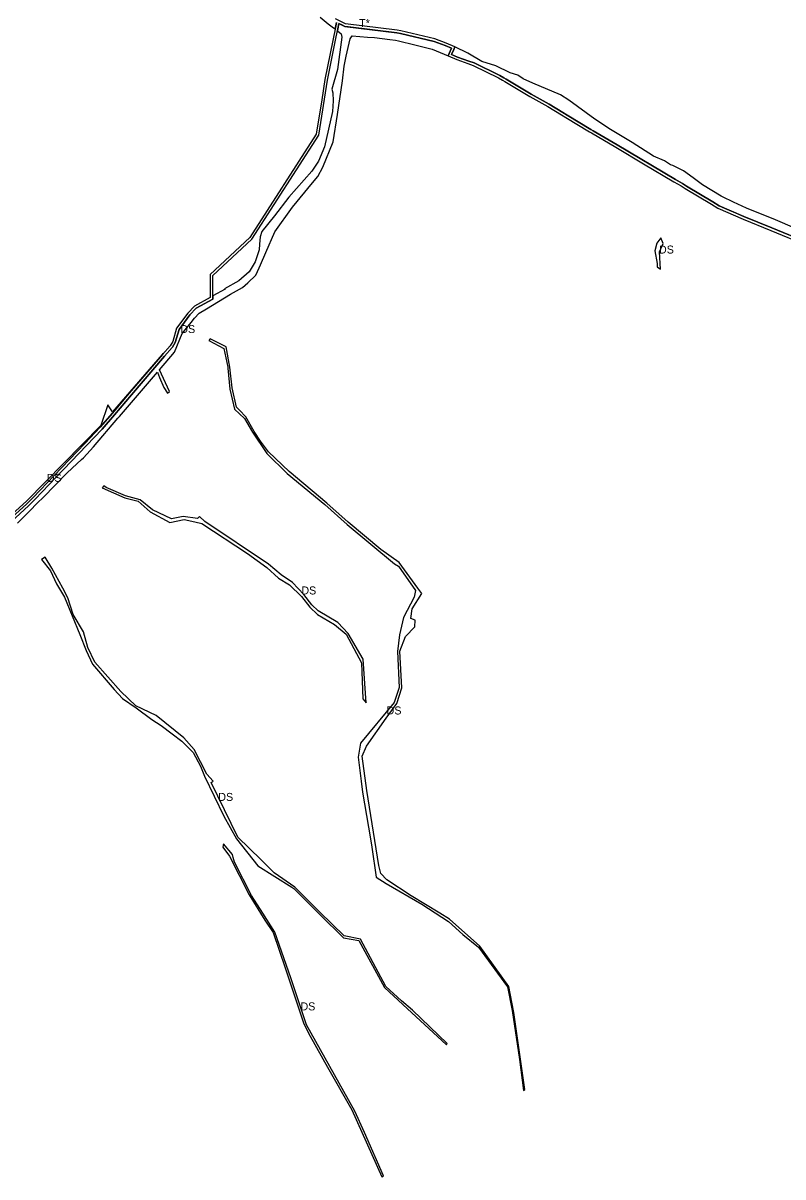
# Model space of a CAD drawing. Extents: x -477304 to -465641, y -1159113 to -1149285.
# Drawn here: x -471518 to -470664, y -1155901 to -1154603 of the extents above; entities that cross this region are included whole.
import ezdxf

# ---------------------------------------------------------------- set-up
doc = ezdxf.new("R2010")
doc.units = 0
doc.layers.add('35', color=7, linetype='Continuous')
doc.layers.add('4', color=7, linetype='Continuous')

msp = doc.modelspace()

# ---------------------------------------------------------------- linework, layer by layer
at = {"layer": '35'}
for p, q in [((-471184.5, -1154596.4), (-471175.4, -1154604.1)), ((-471175.4, -1154604.1), (-471169.4, -1154608.4)), ((-471169.4, -1154608.4), (-471167.6, -1154609.6)), ((-471167.6, -1154609.6), (-471167.3, -1154608.1)), ((-471167.3, -1154608.1), (-471166.1, -1154602.3)), ((-471165, -1154611.8), (-471160.9, -1154615.2)), ((-471159.4, -1154605.6), (-471163.4, -1154603.7)), ((-471155.1, -1154640.2), (-471150.8, -1154620.7)), ((-471150.8, -1154620.7), (-471148.5, -1154617.6)), ((-471148.5, -1154617.6), (-471131.1, -1154619.1)), ((-471131.1, -1154619.1), (-471123.4, -1154619.4)), ((-471123.4, -1154619.4), (-471106.3, -1154621.6)), ((-471106.3, -1154621.6), (-471099.9, -1154622.4)), ((-471099.9, -1154622.4), (-471096.4, -1154622.9)), ((-471096.4, -1154622.9), (-471078, -1154627.5)), ((-471078, -1154627.5), (-471058.5, -1154632.5)), ((-471058.5, -1154632.5), (-471040.6, -1154640.1)), ((-471040.6, -1154640.1), (-471039.4, -1154637.3)), ((-471039.4, -1154637.3), (-471037, -1154631.5)), ((-471034.3, -1154632.8), (-471036.7, -1154638.5)), ((-471036.7, -1154638.5), (-471029.9, -1154641.3)), ((-471033.1, -1154630), (-471034.3, -1154632.8)), ((-471159.4, -1154668.1), (-471157.6, -1154651.6)), ((-471157.6, -1154651.6), (-471155.1, -1154640.2)), ((-471029.9, -1154641.3), (-471017.3, -1154645.8)), ((-470956.4, -1154665.7), (-470962.3, -1154661.8)), ((-471171.4, -1154677.6), (-471170.4, -1154681.6)), ((-471164.8, -1154706.1), (-471159.4, -1154668.1)), ((-470945.2, -1154670.5), (-470956.4, -1154665.7)), ((-471169.9, -1154690.4), (-471170.7, -1154702.4)), ((-471170.4, -1154681.6), (-471169.9, -1154690.4)), ((-471170.7, -1154702.4), (-471179.7, -1154742.1)), ((-470906.8, -1154706.6), (-470880.1, -1154722.7)), ((-470880.1, -1154722.7), (-470877.7, -1154724.1)), ((-470877.7, -1154724.1), (-470850.7, -1154740.1)), ((-470833.8, -1154737.3), (-470857.9, -1154722.9)), ((-470809.7, -1154752.9), (-470833.8, -1154737.3)), ((-470797.3, -1154757.9), (-470809.7, -1154752.9)), ((-471187.1, -1154775.6), (-471181.3, -1154765.1)), ((-471193.9, -1154769.5), (-471219.7, -1154798.8)), ((-471193.1, -1154782.8), (-471187.1, -1154775.6)), ((-470765.3, -1154777.3), (-470776.1, -1154769.4)), ((-470754.5, -1154784.9), (-470765.3, -1154777.3)), ((-471215.7, -1154810.1), (-471193.1, -1154782.8)), ((-471219.7, -1154798.8), (-471235.8, -1154820)), ((-470719.7, -1154804.5), (-470732.2, -1154798.6)), ((-470705.2, -1154811.3), (-470719.7, -1154804.5)), ((-471235.8, -1154820), (-471250, -1154837.5)), ((-471235.4, -1154838), (-471215.7, -1154810.1)), ((-470736, -1154808.6), (-470730, -1154811.3)), ((-470730, -1154811.3), (-470727.3, -1154812.5)), ((-470727.3, -1154812.5), (-470717.7, -1154816.6)), ((-470717.7, -1154816.6), (-470708, -1154820.8)), ((-471252.1, -1154843.4), (-471252.8, -1154851.7)), ((-471250, -1154837.5), (-471252.1, -1154843.4)), ((-471245.7, -1154861.3), (-471235.4, -1154838)), ((-470801.6, -1154844.8), (-470806, -1154850.6)), ((-471253.1, -1154858.2), (-471257.6, -1154871.7)), ((-471252.8, -1154851.7), (-471253.1, -1154858.2)), ((-471257.6, -1154871.7), (-471264.2, -1154882.9)), ((-471251.7, -1154875.1), (-471245.7, -1154861.3)), ((-471264.2, -1154882.9), (-471276, -1154893)), ((-471256.8, -1154886.5), (-471253.2, -1154878.5)), ((-471253.2, -1154878.5), (-471251.7, -1154875.1)), ((-470805.5, -1154873.5), (-470805.7, -1154877.3)), ((-471276, -1154893), (-471291.9, -1154901.8)), ((-471271.8, -1154900.4), (-471265.8, -1154895.2)), ((-471265.8, -1154895.2), (-471256.8, -1154886.5)), ((-471312.1, -1154924.3), (-471285.1, -1154908.1)), ((-471291.4, -1154902.4), (-471305.3, -1154910)), ((-471305.3, -1154910), (-471305.3, -1154913.5)), ((-471291.9, -1154901.8), (-471291.4, -1154902.4)), ((-471285.1, -1154908.1), (-471271.8, -1154900.4)), ((-471320.5, -1154929.3), (-471312.1, -1154924.3)), ((-471329.3, -1154939.7), (-471325.6, -1154935)), ((-471325.6, -1154935), (-471320.5, -1154929.3)), ((-471308, -1154958.1), (-471309.6, -1154960.2)), ((-471290.2, -1154967.1), (-471308, -1154958.1)), ((-471362.2, -1154975.7), (-471417.9, -1155040.4)), ((-471399, -1155019.2), (-471361.7, -1154975.7)), ((-471360.8, -1154974.8), (-471362.2, -1154975.7)), ((-471361.7, -1154975.7), (-471360.8, -1154974.8)), ((-471285.9, -1154990.2), (-471290.2, -1154967.1)), ((-471410, -1155045.4), (-471367.4, -1154995.7)), ((-471367.4, -1154995.7), (-471365, -1155001.6)), ((-471353.9, -1155017.3), (-471365.1, -1154993)), ((-471365, -1155001.6), (-471360.2, -1155013.1)), ((-471283.4, -1155013.3), (-471285.9, -1154990.2)), ((-471360.2, -1155013.1), (-471356.2, -1155019.4)), ((-471285.9, -1155014.7), (-471280.6, -1155037.4)), ((-471278.6, -1155035.1), (-471283.4, -1155013.3)), ((-471356.2, -1155019.4), (-471353.9, -1155017.3)), ((-471423.2, -1155032.4), (-471431, -1155055.7)), ((-471417.9, -1155040.4), (-471423.2, -1155032.4)), ((-471275.3, -1155038.5), (-471278.6, -1155035.1)), ((-471415.8, -1155043.7), (-471429.4, -1155059.7)), ((-471411.8, -1155047.5), (-471410, -1155045.4)), ((-471431, -1155055.7), (-471514.7, -1155140.7)), ((-471449.2, -1155076.1), (-471431.6, -1155057.7)), ((-471251.7, -1155073.4), (-471258.5, -1155062.6)), ((-471242.6, -1155085.4), (-471251.7, -1155073.4)), ((-471452.7, -1155093.8), (-471450.6, -1155091.9)), ((-471496, -1155136.6), (-471468.8, -1155108.8)), ((-471427.5, -1155123.7), (-471429.7, -1155125.8)), ((-471429.7, -1155125.8), (-471404.1, -1155136.9)), ((-471514.7, -1155140.7), (-471548.2, -1155171.2)), ((-471502.1, -1155142.8), (-471496, -1155136.6)), ((-471404.1, -1155136.9), (-471389, -1155140.9)), ((-471389, -1155140.9), (-471375.4, -1155152.8)), ((-471152.9, -1155164.4), (-471176.9, -1155143.1)), ((-471524.9, -1155165.7), (-471513.5, -1155154.3)), ((-471375.4, -1155152.8), (-471353.4, -1155164.7)), ((-471320, -1155157.9), (-471322.2, -1155160.4)), ((-471314.1, -1155163.6), (-471320, -1155157.9)), ((-471353.4, -1155164.7), (-471337.2, -1155161.5)), ((-471317.5, -1155165.8), (-471266.3, -1155199.7)), ((-471116.1, -1155195.1), (-471152.9, -1155164.4)), ((-471493.6, -1155203.7), (-471497.9, -1155206.5)), ((-471497.9, -1155206.5), (-471487.6, -1155219.2)), ((-471486, -1155216.3), (-471493.6, -1155203.7)), ((-471473.8, -1155238.6), (-471486, -1155216.3)), ((-471231.3, -1155227.4), (-471218.8, -1155234.7)), ((-471215.5, -1155232.3), (-471228.3, -1155223.7)), ((-471218.8, -1155234.7), (-471205.6, -1155248.1)), ((-471468, -1155249.4), (-471473.8, -1155238.6)), ((-471471.7, -1155248.7), (-471454.6, -1155290.8)), ((-471205.6, -1155248.1), (-471196.1, -1155259.9)), ((-471077.2, -1155241.2), (-471078.9, -1155248.6)), ((-471164.6, -1155277.2), (-471186.8, -1155264.2)), ((-471077.7, -1155274.8), (-471082.4, -1155272.8)), ((-471445.7, -1155305.2), (-471450.5, -1155287.9)), ((-471153, -1155289.5), (-471164.6, -1155277.2)), ((-471097.7, -1155309.9), (-471095.7, -1155350.5)), ((-471098.3, -1155368.5), (-471092.8, -1155350.8)), ((-471110.1, -1155385), (-471098.3, -1155368.5)), ((-471373.7, -1155386.2), (-471363.2, -1155393)), ((-471132.5, -1155416.4), (-471110.1, -1155385)), ((-471363.2, -1155393), (-471350.8, -1155402.4)), ((-471139.2, -1155412.9), (-471141.6, -1155428.6)), ((-471327.4, -1155423.3), (-471319.1, -1155439)), ((-471319.1, -1155439), (-471314.5, -1155450.1)), ((-471314.5, -1155450.1), (-471292.8, -1155495.1)), ((-471118.6, -1155550.5), (-471132.1, -1155466.1)), ((-471292.8, -1155495.1), (-471278.5, -1155520.7)), ((-471278.5, -1155520.7), (-471254.4, -1155550.8)), ((-471128, -1155520.7), (-471126.5, -1155529.8)), ((-471293.2, -1155526.1), (-471293.9, -1155529.9)), ((-471293.9, -1155529.9), (-471286.3, -1155540)), ((-471283.2, -1155538.3), (-471293.2, -1155526.1)), ((-471286.3, -1155540), (-471264.4, -1155583.7)), ((-471282.3, -1155541.4), (-471283.2, -1155538.3)), ((-471254.4, -1155550.8), (-471216.4, -1155574.8)), ((-471116.3, -1155559.4), (-471118.6, -1155550.5)), ((-471109.6, -1155566.7), (-471116.3, -1155559.4)), ((-471082.1, -1155584.5), (-471109.6, -1155566.7)), ((-471264.4, -1155583.7), (-471246.7, -1155612.1)), ((-471249.1, -1155604.3), (-471261.8, -1155584.4)), ((-471216.4, -1155574.8), (-471214, -1155576.3)), ((-471184.9, -1155603), (-471213.1, -1155574.9)), ((-471050, -1155604.1), (-471082.1, -1155584.5)), ((-470972.3, -1155686.5), (-471005, -1155641.4)), ((-471223.8, -1155665.6), (-471203, -1155728.5)), ((-470973.8, -1155687), (-470968.6, -1155713.7)), ((-470968.6, -1155713.7), (-470960.5, -1155768.8)), ((-471203, -1155728.5), (-471195.6, -1155742.6)), ((-471195.6, -1155742.6), (-471176.1, -1155777.5)), ((-471042.6, -1155752.2), (-471041.7, -1155750.9)), ((-471176.1, -1155777.5), (-471148.9, -1155825.5)), ((-471145.6, -1155827), (-471152.7, -1155814.2)), ((-471134.8, -1155850.8), (-471145.6, -1155827)), ((-471113.2, -1155899.5), (-471134.8, -1155850.8))]:
    msp.add_line(p, q, dxfattribs=at)
for points in [[(-471163.4, -1154603.7), (-471164.5, -1154609.6), (-471165, -1154611.8)], [(-471152.9, -1154607.4), (-471156.6, -1154607), (-471159.4, -1154605.6)], [(-471037, -1154631.5), (-471043.9, -1154628.4), (-471056.3, -1154623.7), (-471094.3, -1154614.7), (-471098.2, -1154614.2), (-471152.9, -1154607.4)], [(-471160.9, -1154615.2), (-471160.2, -1154618.9), (-471164.9, -1154655.3), (-471171.4, -1154677.6)], [(-470962.3, -1154661.8), (-470971, -1154659.1), (-470987, -1154651.2), (-471002.6, -1154646.2), (-471018.3, -1154636.8), (-471033.1, -1154630)], [(-471017.3, -1154645.8), (-471011.4, -1154647.9), (-470982.3, -1154662.1)], [(-470982.3, -1154662.1), (-470977.8, -1154664.8), (-470975.2, -1154666.2), (-470947.4, -1154682.9)], [(-470905, -1154689.8), (-470914.2, -1154683.9), (-470945.2, -1154670.5)], [(-470947.4, -1154682.9), (-470927.1, -1154694.4), (-470911.6, -1154703.7), (-470906.8, -1154706.6)], [(-470857.9, -1154722.9), (-470875.8, -1154711.3), (-470905, -1154689.8)], [(-471181.3, -1154765.1), (-471169.7, -1154736.7), (-471164.8, -1154706.1)], [(-471179.7, -1154742.1), (-471186.5, -1154758.4), (-471193.9, -1154769.5)], [(-470850.7, -1154740.1), (-470785.1, -1154779), (-470777.2, -1154783.7), (-470772.7, -1154786.4)], [(-470776.1, -1154769.4), (-470788, -1154763.1), (-470790.8, -1154762.6), (-470797.3, -1154757.9)], [(-470772.7, -1154786.4), (-470743.2, -1154804.3), (-470736, -1154808.6)], [(-470732.2, -1154798.6), (-470733.6, -1154797.9), (-470754.5, -1154784.9)], [(-470708, -1154820.8), (-470676.7, -1154833.4), (-470636.5, -1154849.9), (-470632.8, -1154851.4)], [(-470650.7, -1154833.6), (-470672.6, -1154824.2), (-470705.2, -1154811.3)], [(-470805.7, -1154877.3), (-470801.8, -1154879.9), (-470803, -1154860.3), (-470798.9, -1154851.1), (-470801.6, -1154844.8)], [(-470806, -1154850.6), (-470808.2, -1154859.2), (-470805.5, -1154873.5)], [(-471305.3, -1154913.5), (-471323.8, -1154923.7), (-471331, -1154931.1)], [(-471331, -1154931.1), (-471343.1, -1154947.7), (-471347.5, -1154962.5), (-471350.6, -1154967.6), (-471350.7, -1154967.9)], [(-471365.1, -1154993), (-471348.2, -1154973.2), (-471339.6, -1154952.2), (-471329.3, -1154939.7)], [(-471309.6, -1154960.2), (-471292.8, -1154968.9), (-471288.3, -1154990.2)], [(-471350.7, -1154967.9), (-471359.4, -1154977.7), (-471396.7, -1155021.2), (-471415.8, -1155043.7)], [(-471288.3, -1154990.2), (-471288.2, -1154991.1), (-471285.9, -1155014.7)], [(-471431.6, -1155057.7), (-471418.1, -1155041.8), (-471399, -1155019.2)], [(-471280.6, -1155037.4), (-471269.5, -1155047.8), (-471260.7, -1155063.3), (-471244.3, -1155087.2), (-471221.6, -1155109.8), (-471179.1, -1155144.4), (-471154.1, -1155167.1), (-471100.8, -1155211.1), (-471096.4, -1155214), (-471077.2, -1155241.2)], [(-471258.5, -1155062.6), (-471268, -1155045.9), (-471275.3, -1155038.5)], [(-471450.6, -1155091.9), (-471439.3, -1155079.6), (-471411.8, -1155047.5)], [(-471429.4, -1155059.7), (-471447.1, -1155078.2), (-471481.2, -1155113.9), (-471504.9, -1155138.7)], [(-471507, -1155136.6), (-471483.4, -1155111.8), (-471449.2, -1155076.1)], [(-471176.9, -1155143.1), (-471219.4, -1155107.5), (-471242.6, -1155085.4)], [(-471468.8, -1155108.8), (-471458, -1155098.8), (-471452.7, -1155093.8)], [(-471386.8, -1155139.2), (-471403.3, -1155134.6), (-471425.2, -1155125.3), (-471427.5, -1155123.7)], [(-471597.2, -1155216), (-471589.1, -1155208.2), (-471582.5, -1155201.6), (-471548, -1155174.3), (-471514.2, -1155143.7), (-471507, -1155136.6)], [(-471504.9, -1155138.7), (-471512.2, -1155145.9), (-471546.1, -1155176.6), (-471580.5, -1155203.9), (-471587, -1155210.4)], [(-471513.5, -1155154.3), (-471511.3, -1155152.1), (-471502.1, -1155142.8)], [(-471351.5, -1155160.7), (-471373, -1155150.6), (-471386.8, -1155139.2)], [(-471322.2, -1155160.4), (-471338.6, -1155158), (-471351.5, -1155160.7)], [(-471337.2, -1155161.5), (-471325.3, -1155164.1), (-471317.5, -1155165.8)], [(-471228.3, -1155223.7), (-471242.6, -1155211.8), (-471314.1, -1155163.6)], [(-471074.5, -1155238.5), (-471095.6, -1155209.9), (-471116.1, -1155195.1)], [(-471266.3, -1155199.7), (-471244.4, -1155215.2), (-471231.3, -1155227.4)], [(-471487.6, -1155219.2), (-471480.8, -1155233.8), (-471471.7, -1155248.7)], [(-471186.8, -1155264.2), (-471193.9, -1155257.5), (-471202.9, -1155245.9), (-471215.5, -1155232.3)], [(-471078.9, -1155248.6), (-471090.9, -1155271.7), (-471095.4, -1155291.1), (-471097.7, -1155309.9)], [(-471082.4, -1155272.8), (-471080.9, -1155261.7), (-471070, -1155244.6), (-471074.5, -1155238.5)], [(-471450.5, -1155287.9), (-471462.1, -1155268.2), (-471468, -1155249.4)], [(-471196.1, -1155259.9), (-471187.4, -1155268.1), (-471168.5, -1155279.6)], [(-471088.4, -1155293.1), (-471078.1, -1155282.3), (-471077.7, -1155274.8)], [(-471168.5, -1155279.6), (-471155.3, -1155290.3), (-471137.9, -1155322.6), (-471136.5, -1155363.2), (-471132.9, -1155367.6)], [(-471454.6, -1155290.8), (-471447.6, -1155308.8), (-471440.3, -1155324.1)], [(-471132.9, -1155367.6), (-471136, -1155318.3), (-471153, -1155289.5)], [(-471092.8, -1155350.8), (-471095, -1155309.6), (-471088.4, -1155293.1)], [(-471408.7, -1155354.9), (-471437.9, -1155321.8), (-471445.7, -1155305.2)], [(-471440.3, -1155324.1), (-471416.2, -1155352.7), (-471406.8, -1155362.8), (-471391.3, -1155373.2), (-471373.7, -1155386.2)], [(-471095.7, -1155350.5), (-471101.4, -1155367.2), (-471139.2, -1155412.9)], [(-471369, -1155381.8), (-471391.5, -1155371.1), (-471408.7, -1155354.9)], [(-471304.9, -1155455.8), (-471311.7, -1155447.9), (-471326.1, -1155419.9), (-471337.6, -1155407), (-471369, -1155381.8)], [(-471350.8, -1155402.4), (-471340, -1155410.6), (-471327.4, -1155423.3)], [(-471132.1, -1155466.1), (-471137.1, -1155427.4), (-471132.5, -1155416.4)], [(-471141.6, -1155428.6), (-471138.4, -1155455.8), (-471136.7, -1155468.1), (-471128, -1155520.7)], [(-471251.3, -1155543.6), (-471277.2, -1155518.6), (-471306.9, -1155457.1), (-471304.9, -1155455.8)], [(-471126.5, -1155529.8), (-471121.5, -1155563.7), (-471110.3, -1155570.8), (-471070.2, -1155594.2)], [(-471261.8, -1155584.4), (-471280.7, -1155546.8), (-471282.3, -1155541.4)], [(-471213.1, -1155574.9), (-471236.1, -1155558.6), (-471251.3, -1155543.6)], [(-471214, -1155576.3), (-471184, -1155606.5), (-471158.1, -1155631.9)], [(-471070.2, -1155594.2), (-471040.2, -1155613.6), (-471024, -1155628.1)], [(-471217.3, -1155676.7), (-471235.4, -1155625.5), (-471249.1, -1155604.3)], [(-471246.7, -1155612.1), (-471237.3, -1155625.9), (-471223.8, -1155665.6)], [(-471139.2, -1155633.3), (-471157.5, -1155629.7), (-471184.9, -1155603)], [(-471005, -1155641.4), (-471038.9, -1155610.9), (-471050, -1155604.1)], [(-471158.1, -1155631.9), (-471141, -1155635), (-471112.1, -1155687.9)], [(-471093.2, -1155702.8), (-471110.5, -1155686.5), (-471139.2, -1155633.3)], [(-471024, -1155628.1), (-471006.6, -1155642.5), (-470973.8, -1155687)], [(-471152.7, -1155814.2), (-471199.9, -1155729.8), (-471217.3, -1155676.7)], [(-471112.1, -1155687.9), (-471091.6, -1155707), (-471042.6, -1155752.2)], [(-470954.2, -1155802.5), (-470966.6, -1155715.7), (-470972.3, -1155686.5)], [(-471041.7, -1155750.9), (-471080.8, -1155713.1), (-471093.2, -1155702.8)], [(-470960.5, -1155768.8), (-470955.8, -1155803.4), (-470954.2, -1155802.5)], [(-471148.9, -1155825.5), (-471115.1, -1155900.8), (-471113.2, -1155899.5)]]:
    msp.add_lwpolyline(points, dxfattribs=at)
at = {"layer": '4'}
for p, q in [((-471166.1, -1154602.3), (-471167.3, -1154608.1)), ((-471039.4, -1154637.3), (-471040.6, -1154640.1)), ((-471037, -1154631.5), (-471039.4, -1154637.3)), ((-471036.7, -1154638.5), (-471034.3, -1154632.8)), ((-471029.9, -1154641.3), (-471036.7, -1154638.5)), ((-471034.3, -1154632.8), (-471033.1, -1154630)), ((-471040.6, -1154640.1), (-471031, -1154644.1)), ((-471031, -1154644.1), (-471018.3, -1154648.6)), ((-471017.3, -1154645.8), (-471029.9, -1154641.3)), ((-471018.3, -1154648.6), (-471012.5, -1154650.7)), ((-471012.5, -1154650.7), (-470983.8, -1154664.7)), ((-471186, -1154729.1), (-471176.1, -1154667.2)), ((-470976.7, -1154668.8), (-470948.9, -1154685.5)), ((-470948.9, -1154685.5), (-470928.6, -1154697)), ((-470928.6, -1154697), (-470913.2, -1154706.2)), ((-470913.2, -1154706.2), (-470908.3, -1154709.2)), ((-470908.3, -1154709.2), (-470881.6, -1154725.3)), ((-470880.1, -1154722.7), (-470906.8, -1154706.6)), ((-470881.6, -1154725.3), (-470879.3, -1154726.7)), ((-470877.7, -1154724.1), (-470880.1, -1154722.7)), ((-470879.3, -1154726.7), (-470852.2, -1154742.7)), ((-470850.7, -1154740.1), (-470877.7, -1154724.1)), ((-470852.2, -1154742.7), (-470820.9, -1154761.3)), ((-470820.9, -1154761.3), (-470786.7, -1154781.6)), ((-470786.7, -1154781.6), (-470778.7, -1154786.3)), ((-470778.7, -1154786.3), (-470774.3, -1154789)), ((-470774.3, -1154789), (-470744.7, -1154806.9)), ((-470744.7, -1154806.9), (-470737.4, -1154811.3)), ((-470737.4, -1154811.3), (-470709.1, -1154823.6)), ((-470708, -1154820.8), (-470736, -1154808.6)), ((-470709.1, -1154823.6), (-470677.8, -1154836.2)), ((-471263.7, -1154844.1), (-471308.3, -1154885.7)), ((-470677.8, -1154836.2), (-470637.6, -1154852.7)), ((-471308.3, -1154885.7), (-471308.3, -1154911.7)), ((-471305.3, -1154913.5), (-471305.3, -1154887)), ((-471361.7, -1154975.7), (-471399, -1155019.2)), ((-471353.1, -1154966.1), (-471361.7, -1154975.7)), ((-471353.1, -1154966.1), (-471353.1, -1154966.1)), ((-471429.4, -1155059.7), (-471415.8, -1155043.7)), ((-471431.6, -1155057.7), (-471449.2, -1155076.1))]:
    msp.add_line(p, q, dxfattribs=at)
for points in [[(-471033.1, -1154630), (-471042.7, -1154625.6), (-471055.4, -1154620.9), (-471093.7, -1154611.7), (-471097.8, -1154611.2), (-471155.8, -1154604.1), (-471167.2, -1154598.5)], [(-471167.3, -1154608.1), (-471179.1, -1154666.6), (-471182.7, -1154689.6), (-471188.8, -1154728), (-471263.7, -1154844.1)], [(-471176.1, -1154667.2), (-471167.5, -1154624.1), (-471164.5, -1154609.6), (-471163.4, -1154603.7)], [(-471163.4, -1154603.7), (-471156.6, -1154607), (-471098.2, -1154614.2), (-471094.3, -1154614.7), (-471056.3, -1154623.7), (-471043.9, -1154628.4), (-471037, -1154631.5)], [(-470982.3, -1154662.1), (-471011.4, -1154647.9), (-471017.3, -1154645.8)], [(-470983.8, -1154664.7), (-470979.3, -1154667.4), (-470976.7, -1154668.8)], [(-470947.4, -1154682.9), (-470975.2, -1154666.2), (-470977.8, -1154664.8), (-470982.3, -1154662.1)], [(-470906.8, -1154706.6), (-470911.6, -1154703.7), (-470927.1, -1154694.4), (-470947.4, -1154682.9)], [(-471305.3, -1154887), (-471261.4, -1154846), (-471186, -1154729.1)], [(-470772.7, -1154786.4), (-470777.2, -1154783.7), (-470785.1, -1154779), (-470850.7, -1154740.1)], [(-470736, -1154808.6), (-470743.2, -1154804.3), (-470772.7, -1154786.4)], [(-470632.8, -1154851.4), (-470636.5, -1154849.9), (-470676.7, -1154833.4), (-470708, -1154820.8)], [(-471308.3, -1154911.7), (-471325.7, -1154921.3), (-471333.3, -1154929.2), (-471345.9, -1154946.4)], [(-471331, -1154931.1), (-471323.8, -1154923.7), (-471305.3, -1154913.5)], [(-471350.7, -1154967.9), (-471350.6, -1154967.6), (-471347.5, -1154962.5), (-471343.1, -1154947.7), (-471331, -1154931.1)], [(-471345.9, -1154946.4), (-471350.2, -1154961.3), (-471353.1, -1154966.1)], [(-471415.8, -1155043.7), (-471396.7, -1155021.2), (-471359.4, -1154977.7), (-471350.7, -1154967.9)], [(-471399, -1155019.2), (-471418.1, -1155041.8), (-471431.6, -1155057.7)], [(-471504.9, -1155138.7), (-471481.2, -1155113.9), (-471447.1, -1155078.2), (-471429.4, -1155059.7)], [(-471449.2, -1155076.1), (-471483.4, -1155111.8), (-471507, -1155136.6)], [(-471507, -1155136.6), (-471514.2, -1155143.7), (-471548, -1155174.3), (-471582.5, -1155201.6), (-471589.1, -1155208.2), (-471597.2, -1155216)], [(-471587, -1155210.4), (-471580.5, -1155203.9), (-471546.1, -1155176.6), (-471512.2, -1155145.9), (-471504.9, -1155138.7)]]:
    msp.add_lwpolyline(points, dxfattribs=at)

# ---------------------------------------------------------------- texts
at = {"layer": '35'}
for p in [(-470803.6, -1154862.3), (-471341.7, -1154951.7), (-471491.9, -1155119.1), (-471205.6, -1155245.7), (-471109.8, -1155380.7), (-471299, -1155477.9), (-471206.6, -1155713.5)]:
    msp.add_text('DS', height=9, dxfattribs=at).set_placement(p)
at = {"layer": '4'}
msp.add_text('T*', height=9, dxfattribs=at).set_placement((-471140.6, -1154607.6))

doc.saveas('drawing.dxf')
